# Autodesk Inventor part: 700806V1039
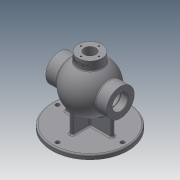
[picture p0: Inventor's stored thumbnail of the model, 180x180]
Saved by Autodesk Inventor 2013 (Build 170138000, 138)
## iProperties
Created: 2020-08
Part Number: 700806V1039
Material: 일반
Document SubType Name: Modeling
Designer: user
Density: 1 g/cm^3
Mass: 649.177 g
Surface Area: 1342.89 cm^2
Volume: 649.177 cm^3
Author: user
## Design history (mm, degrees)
sketch "스케치1"
  geometry: L1 (-68, 0)-(68, 0); L2 (-68, 31)-(-68, 17.5); L3 (68, 31)-(68, 17.5); L4 (-68, 31)-(-42.988, 31); L5 (42.988, 31)-(68, 31); L6 (-68, 17.5)-(-39.278, 17.5); L7 (39.278, 17.5)-(50.25, 17.5); L8 (50.25, 17.5)-(50.25, 18.5); L9 (50.25, 18.5)-(52, 18.5); L10 (52, 18.5)-(52, 17.5); L11 (52, 17.5)-(68, 17.5); A1 r 53 centre (0, 0) between (42.988, 31) and (-42.988, 31); A2 r 43 centre (0, 0) between (39.278, 17.5) and (-39.278, 17.5); 2 further points
  constraints: 22 end point, 4 perpendicular, 4 point on circle, 3 coincident, 3 parallel, 2 centre point, 2 collinear, 2 point on line, 1 horizontal, 1 midpoint
  dimensions: "d0" = 136 distance of L1.start L1.end; "d2" = 106 diameter of A1; "d6" = 62 diameter of L4 L1; "d8" = 62 diameter of L5 L1; "d9" = 86 diameter of A2; "d96" = 35 diameter of L6 L1; "d97" = 35 diameter of L11 L1; "d98" = 35 diameter of L7 L1; "d99" = 37 diameter of L9 L1; "d100" = 16 distance between parallel lines of L3 L10; "d101" = 1.75 distance between parallel lines of L10 L8
revolve "회전1" sketch "스케치1" stored, may be unused: angle "d10" = 90 deg
node "작업 평면1"
sketch "스케치2"
  geometry: C1 r 85 at (0, 0); 1 further point
  constraints: 1 centre point, 1 coincident
  dimensions: "d12" = 170 diameter of C1
extrude "돌출1" join sketch "스케치2" distance "d13" = 10; taper "d14" = 0 deg
sketch "스케치3"
  geometry: L1 (52, 4)-(-52, 4); L2 (-52, 4)-(-52, -4); L3 (-52, -4)-(52, -4); L4 (52, -4)-(52, 4); L5 (52, 4)-(-52, -4); L6 (-52, 4)-(52, -4); C1 r 85 at (0, 0) reference
  constraints: 12 end point, 2 midpoint, 2 parallel, 1 horizontal, 1 perpendicular
  dimensions: "d15" = 104 distance of L3.end L2.end; "d16" = 8 distance of L2.end L1.end
extrude "돌출2" join sketch "스케치3" stored distance "d17" = 0; taper "d18" = 0 deg
node "작업 평면2"
sketch "스케치5"
  geometry: C1 r 27 at (0, 0); 1 further point
  constraints: 1 centre point, 1 coincident
  dimensions: "d24" = 54 diameter of C1
extrude "돌출4" join sketch "스케치5" stored distance "d25" = 10; taper "d26" = 0 deg
sketch "스케치6"
  geometry: C1 r 27 at (0, 0) reference; C2 r 13 at (0, 0)
  constraints: 1 centre point, 1 coincident
  dimensions: "d27" = 26 diameter of C2
extrude "돌출5" cut sketch "스케치6" stored distance "d28" = 10; taper "d29" = 0 deg
sketch "스케치7"
  geometry: L1 (4, -43)-(-4, -43); L2 (-4, -43)-(-4, 43); L3 (-4, 43)-(4, 43); L4 (4, 43)-(4, -43); L5 (4, -43)-(-4, 43); L6 (-4, -43)-(4, 43); C1 r 85 at (0, 0) reference
  constraints: 12 end point, 2 midpoint, 2 parallel, 1 horizontal, 1 perpendicular
  dimensions: "d30" = 8 distance of L2.end L3.end; "d31" = 86 distance of L1.end L2.end
extrude "돌출6" join sketch "스케치7" stored distance "d32" = 10; taper "d33" = 0 deg
node "작업 평면3"
sketch "스케치8"
  geometry: L1 (-27, 65)-(27, 65) reference; L2 (-27, 45.607)-(27, 45.607) reference; L3 (-27, 65)-(27, 65) reference; 2 further points
  constraints: 1 other
  dimensions: "d35" = 9 distance from line of L1 point (0, 56); "d37" = 27 horizontal distance of point (0, 56) L1.start
feature "엠보싱1" sketch "스케치8" dims "d15" = 104, "d16" = 8, "d38" = 0.5, "d39" = 0
chamfer "모따기1" distance "d45" = 1; stored, may be unused: second distance "d46" = 2, angle "d47" = 45 deg
fillet "모깎기1" dims "d48" = 3
fillet "모깎기2" dims "d49" = 3
fillet "모깎기3" dims "d50" = 3
fillet "모깎기4" dims "d51" = 3
sketch "스케치9"
  geometry: C1 r 13 at (0, 0) reference; 1 further point
  constraints: 1 horizontal alignment
  dimensions: "d52" = 20 distance of point (20, 0) C1.centre
hole "구멍1" sketch "스케치9" at (20, 0) diameter "d53" = 3.242; stored, may be unused: countersink angle "d57" = 90 deg, drill point angle "d59" = 118 deg; dims "d54" = 12, "d55" = 4, "d56" = 2, "d58" = 15
sketch "스케치10"
  geometry: C1 r 31 at (0, 0) reference; 1 further point
  constraints: 1 vertical alignment
  dimensions: "d63" = 24 distance of point (0, 24) C1.centre
hole "구멍2" sketch "스케치10" at (0, 24) diameter "d64" = 3.242; stored, may be unused: countersink angle "d68" = 90 deg, drill point angle "d70" = 118 deg; dims "d65" = 12, "d66" = 4, "d67" = 2, "d69" = 15
sketch "스케치11"
  geometry: C1 r 31 at (0, 0) reference; 1 further point
  constraints: 1 vertical alignment
  dimensions: "d74" = 24 distance of point (0, 24) C1.centre
hole "구멍3" sketch "스케치11" at (0, 24) diameter "d75" = 3.242; stored, may be unused: countersink angle "d79" = 90 deg, drill point angle "d81" = 118 deg; dims "d76" = 12, "d77" = 4, "d78" = 2, "d80" = 15
sketch "스케치12"
  geometry: C1 r 82 at (0, 0) reference; 1 further point
  constraints: 1 vertical alignment
  dimensions: "d85" = 72.5 distance of point (0, 72.5) C1.centre
hole "구멍4" sketch "스케치12" at (0, 72.5) diameter "d86" = 9; stored, may be unused: countersink angle "d90" = 90 deg, drill point angle "d92" = 118 deg; dims "d87" = 12, "d88" = 4, "d89" = 2, "d91" = 15
chamfer "모따기2" distance "d102" = 1; stored, may be unused: second distance "d103" = 2, angle "d104" = 45 deg
node "솔리드1"
pattern_circular "원형 패턴1" dims angle "d61" = 360 deg
pattern_circular "원형 패턴2" dims angle "d72" = 360 deg
pattern_circular "원형 패턴3" dims angle "d83" = 360 deg
pattern_circular "원형 패턴4" dims angle "d94" = 360 deg
node "투영된 루프1"
other parameters: "d3" = 62, "d11" = -85, "d34" = 27
